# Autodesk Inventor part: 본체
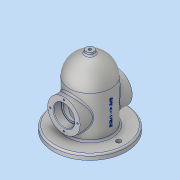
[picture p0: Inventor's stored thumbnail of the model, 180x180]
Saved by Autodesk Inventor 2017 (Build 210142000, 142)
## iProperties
Created: 2019-11
Part Number: 본체
Material: Aluminum 6061
Document SubType Name: Modeling
Designer: 1-17-lg
Density: 2.7 g/cm^3
Appearance: Aluminum - Flat
Author: 1-17-lg
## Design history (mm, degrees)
sketch "Sketch2"
  geometry: C1 r 70 at (0, 0); 1 further point
  constraints: 1 centre point, 1 coincident
  dimensions: "d0" = 140 diameter of C1
extrude "Extrusion1" new body sketch "Sketch2" distance "d1" = 10; taper "d2" = 0 deg
sketch "Sketch4"
  geometry: L1 (0, 90)-(40, 90); L2 (40, 90)-(40, 0); L3 (-70, 0)-(70, 0) reference; L4 (0, 0)-(40, 0); L5 (0, 0)-(0, 130); A1 r 40 centre (0, 90) between (40, 90) and (0, 130)
  constraints: 8 end point, 2 perpendicular, 2 point on circle, 1 centre point, 1 point on line, 1 vertical
  dimensions: "d4" = 90 distance of L4.start L1.start; "d5" = 40 distance of L1.end L1.start
revolve "Revolution1" sketch "Sketch4" stored, may be unused: angle "d6" = 90 deg
workplane "Work Plane1"
sketch "Sketch5"
  geometry: C1 r 7.5 at (0, 0); 1 further point
  constraints: 1 centre point, 1 coincident
  dimensions: "d8" = 15 diameter of C1
extrude "Extrusion2" join sketch "Sketch5" stored distance "d9" = 10; taper "d10" = 0 deg
sketch "Sketch7"
  geometry: L1 (0, 0)-(0, 50); C1 r 31 at (0, 50)
  constraints: 2 end point, 1 centre point, 1 coincident, 1 vertical
  dimensions: "d14" = 50 distance of L1.start L1.end; "d15" = 62 diameter of C1
extrude "Extrusion3" join sketch "Sketch7" stored distance "d16" = 100; taper "d17" = 0 deg
sketch "Sketch8"
  geometry: L1 (0, 90)-(30, 90); L2 (30, 90)-(30, 0); L3 (30, 0)-(0, 0); L4 (0, 0)-(0, 120); A1 r 30 centre (0, 90) between (30, 90) and (0, 120)
  constraints: 8 end point, 2 perpendicular, 2 point on circle, 1 centre point, 1 coincident, 1 vertical
  dimensions: "d19" = 30 distance of L1.end L1.start
revolve "Revolution3" sketch "Sketch8" stored, may be unused: angle "d20" = 90 deg
sketch "Sketch11"
  geometry: C1 r 31 at (0, 0) reference; C2 r 16.5 at (0, 0); 1 further point
  constraints: 1 centre point, 1 coincident
  dimensions: "d21" = 33 diameter of C2
extrude "Extrusion4" cut sketch "Sketch11" stored distance "d22" = 100; taper "d23" = 0 deg
sketch "Sketch12"
  geometry: C1 r 31 at (0, 0) reference; C2 r 20 at (0, 0); 1 further point
  constraints: 1 centre point, 1 coincident
  dimensions: "d24" = 40 diameter of C2
extrude "Extrusion5" cut sketch "Sketch12" distance "d25" = 15; taper "d26" = 0 deg
mirror "Mirror1"
sketch "Sketch13"
  geometry: C1 r 7.5 at (0, 0) reference; 1 further point
  constraints: 1 coincident
hole "Hole1" sketch "Sketch13" at (0, 0) diameter "d27" = 5.188; stored, may be unused: countersink angle "d31" = 90 deg, drill point angle "d33" = 118 deg; dims "d28" = 12, "d29" = 4, "d30" = 2, "d32" = 16
sketch "Sketch14" dims "d34" = 52
  geometry: L1 (0, 0)-(0, 26); C1 r 31 at (0, 0) reference; 2 further points
  constraints: 2 coincident, 2 end point, 1 vertical, 1 vertical alignment, 2 other
hole "Hole2" sketch "Sketch14" at (0, 26) diameter "d35" = 3.242; stored, may be unused: countersink angle "d39" = 90 deg, drill point angle "d41" = 118 deg; dims "d36" = 8, "d37" = 4, "d38" = 2, "d40" = 10
pattern_circular "Circular Pattern1" dims angle "d43" = 360 deg
mirror "Mirror2"
sketch "Sketch15"
  geometry: L1 (-55, 0)-(55, 0); C1 r 7.5 at (0, 0) reference; C2 r 4.5 at (-55, 0); C3 r 4.5 at (55, 0); A1 r 55 centre (0, 0) between (-55, 0) and (55, 0)
  constraints: 3 centre point, 3 coincident, 2 end point, 2 point on circle
  dimensions: "d45" = 110 diameter of A1; "d46" = 9 diameter of C2; "d47" = 9 diameter of C3
extrude "Extrusion6" cut sketch "Sketch15" stored distance "d48" = 15; taper "d49" = 0 deg
workplane "Work Plane2"
sketch "Sketch16"
  geometry: L1 (53.055, 40)-(53.055, -40); L2 (53.055, -40)-(46.945, -40); L3 (46.945, -40)-(46.945, 40); L4 (46.945, 40)-(53.055, 40); L5 (0, 0)-(50, 0); L6 (50, -40)-(50, 40); L7 (53.055, 0)-(46.945, 0); L8 (90, -40)-(10, -40) reference; L9 (90, 40)-(10, 40) reference
  constraints: 6 end point, 6 midpoint, 1 horizontal, 2 other
  dimensions: "d51" = 50 distance of L5.end L5.start
emboss "Emboss1" sketch "Sketch16" dims "d52" = 0.5, "d53" = 0
fillet "Fillet1" dims "d54" = 3, "d55" = 0.3
chamfer "Chamfer1" distance "d56" = 1; stored, may be unused: second distance "d57" = 2, angle "d58" = 45 deg
chamfer "Chamfer2" distance "d59" = 1; stored, may be unused: second distance "d60" = 2, angle "d61" = 45 deg
body "Solid1"
other parameters: "d7" = 135
